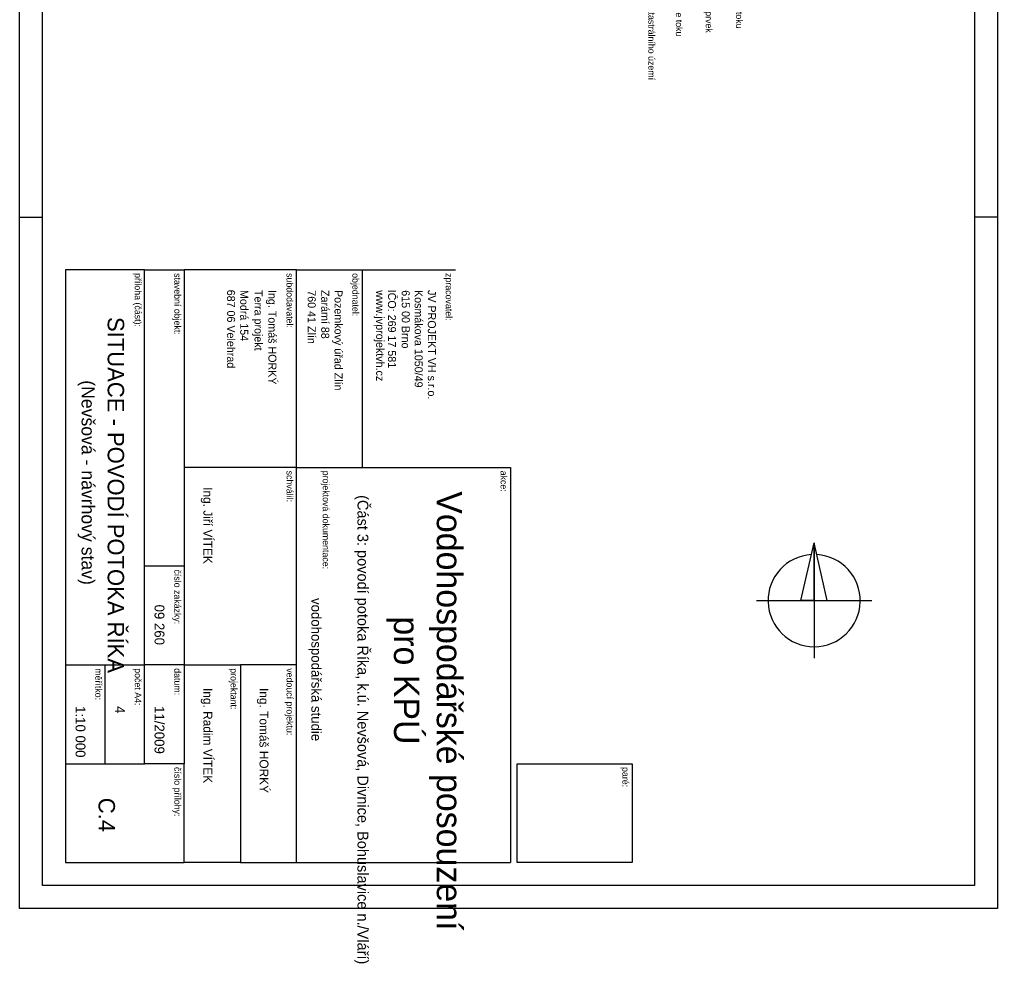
# Model space of a CAD drawing. Extents: x -510989 to -501240, y -1184665 to -1176089.
# Drawn here: x -510989 to -508019, y -1184665 to -1181798 of the extents above; entities that cross this region are included whole.
import ezdxf

# ---------------------------------------------------------------- set-up
doc = ezdxf.new("R2010")
doc.units = 0
for name, color, linetype in [('Implicitní', 7, 'Continuous'), ('legenda', 7, 'Continuous'), ('rozpiska', 7, 'Continuous')]:
    doc.layers.add(name, color=color, linetype=linetype)

# ---------------------------------------------------------------- blocks, each defined once
blk = doc.blocks.new('rozpiska-cary')
at = {"layer": 'Implicitní'}
for p, q in [((-0.03, -0.035), (-0.03, 0)), ((-0.03, 0), (0, 0)), ((0, 0), (0, -0.035)), ((0, -0.035), (-0.03, -0.035)), ((-0.12, -0.102), (-0.12, -0.037)), ((-0.12, -0.037), (0, -0.037)), ((0, -0.102), (0, -0.037)), ((-0.18, -0.082), (-0.18, -0.05365)), ((-0.18, -0.102), (-0.18, -0.082)), ((-0.18, -0.082), (-0.12, -0.082)), ((-0.12, -0.102), (-0.18, -0.102)), ((-0.18, -0.102), (-0.18, -0.1361)), ((-0.06, -0.102), (-0.12, -0.102)), ((-0.12, -0.102), (-0.12, -0.1361)), ((0, -0.102), (-0.06, -0.102)), ((-0.06, -0.102), (-0.06, -0.119)), ((0, -0.119), (0, -0.102)), ((-0.06, -0.13609), (-0.06, -0.119)), ((-0.06, -0.119), (0, -0.119)), ((0, -0.119), (0, -0.1361)), ((-0.18, -0.14809), (-0.18, -0.13609)), ((-0.18, -0.13609), (-0.09, -0.13609)), ((-0.09, -0.13609), (-0.09, -0.14809)), ((-0.09, -0.13609), (-0.06, -0.13609)), ((-0.06, -0.13609), (-0.06, -0.14809)), ((-0.06, -0.13609), (-0.03, -0.13609)), ((0, -0.13609), (-0.03, -0.13609)), ((-0.03, -0.13609), (-0.03, -0.14809)), ((0, -0.17209), (0, -0.13609)), ((-0.06, -0.14809), (-0.18, -0.14809)), ((-0.18, -0.14809), (-0.18, -0.17209)), ((-0.06, -0.17209), (-0.06, -0.14809)), ((-0.03, -0.14809), (-0.06, -0.14809)), ((-0.03, -0.16009), (-0.03, -0.14809)), ((-0.03, -0.16009), (-0.06, -0.16009)), ((-0.03, -0.17209), (-0.03, -0.16009)), ((-0.18, -0.17209), (-0.06, -0.17209)), ((-0.06, -0.17209), (-0.03, -0.17209)), ((-0.03, -0.17209), (0, -0.17209))]:
    blk.add_line(p, q, dxfattribs=at)

msp = doc.modelspace()

# ---------------------------------------------------------------- linework, layer by layer
at = {"layer": 'rozpiska'}
for p, q in [((-510989.09, -1182398), (-510919.09, -1182398)), ((-508019.09, -1182398), (-508089.09, -1182398)), ((-508615.85, -1183562.57), (-508575.85, -1183387.57)), ((-508575.85, -1183562.57), (-508575.85, -1183387.57)), ((-508535.85, -1183562.57), (-508575.85, -1183387.57)), ((-508750.85, -1183562.57), (-508400.85, -1183562.57)), ((-508575.85, -1183562.57), (-508615.85, -1183562.57)), ((-508575.85, -1183562.57), (-508575.85, -1183737.57)), ((-508575.85, -1183562.57), (-508535.85, -1183562.57))]:
    msp.add_line(p, q, dxfattribs=at)
for points in [[(-508019.09, -1176098), (-508019.09, -1184498), (-510989.09, -1184498), (-510989.09, -1176098)], [(-508089.09, -1176168), (-508089.09, -1184428), (-510919.09, -1184428), (-510919.09, -1176168)], [(-508575.85, -1183562.57), (-508535.85, -1183562.57), (-508575.85, -1183387.57)]]:
    msp.add_lwpolyline(points, close=True, dxfattribs=at)
msp.add_lwpolyline([(-508575.85, -1183562.57), (-508535.85, -1183562.57), (-508575.85, -1183387.57)], dxfattribs=at)
msp.add_arc((-508575.85, -1183562.57), 140, 93.29755, 86.70245, dxfattribs=at)

# ---------------------------------------------------------------- block references
at = {"layer": 'rozpiska', "xscale": 10000, "yscale": 10000, "rotation": -90.00000000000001}
msp.add_blockref('rozpiska-cary', (-509128.22, -1184358), dxfattribs=at)

# ---------------------------------------------------------------- texts
at = {"layer": 'legenda'}
for s, p in [('Hranice katastrálního území', (-509079.29, -1181648.76)), ('Revitalizace toku', (-508995.74, -1181646.93)), ('Interakční prvek', (-508904.97, -1181647.71)), ('Trasování toku', (-508813.03, -1181648.38))]:
    msp.add_text(s, height=20, rotation=270, dxfattribs=at).set_placement(p)
at = {"layer": 'rozpiska'}
for s, height, p in [('příloha (část):', 20, (-510639.09, -1182568)), ('stavební objekt:', 20, (-510519.09, -1182568)), ('subdodavatel:', 20, (-510178.22, -1182568)), ('objednatel:', 20, (-509978.22, -1182568)), ('zpracovatel:', 20, (-509694.76, -1182568)), ('687 06 Velehrad', 24.3, (-510358.84, -1182618.37)), ('Modrá 154', 24.3, (-510318.91, -1182619.22)), ('Terra projekt', 24.3, (-510275.44, -1182619.22)), ('Ing. Tomáš HORKÝ', 24.3, (-510233.34, -1182619.22)), ('760 41 Zlín', 24.3, (-510113.84, -1182620.09)), ('Zarámí 88', 24.3, (-510072.88, -1182619.22)), ('Pozemkový úřad Zlín', 24.3, (-510032.52, -1182619.22)), ('www.jvprojektvh.cz', 24.3, (-509906.04, -1182620.12)), ('IČO: 269 17 581', 24.3, (-509870.11, -1182618.28)), ('615 00 Brno', 24.3, (-509828.3, -1182619.94)), ('Kosmákova 1050/49', 24.3, (-509789.04, -1182619.22)), ('JV PROJEKT VH s.r.o.', 24.3, (-509749.06, -1182619.22)), ('SITUACE - POVODÍ POTOKA ŘÍKA', 50, (-510721.53, -1182701.26)), ('(Nevšová - návrhový stav)', 40, (-510800.68, -1182893.51)), ('schválil:', 20, (-510178.22, -1183168)), ('projektová dokumentace:', 20, (-510068.22, -1183168)), ('akce:', 20, (-509528.22, -1183168)), ('Ing. Jiří VÍTEK', 27, (-510430.65, -1183218)), ('(Část 3: povodí potoka Říka, k.ú. Nevšová, Divnice, Bohuslavice n./Vláří)', 33, (-509962.72, -1183242.23)), ('Vodohospodářské posouzení', 77, (-509721.84, -1183230.44)), ('číslo zakázky:', 20, (-510519.09, -1183468)), ('vodohospodářská studie', 30, (-510102.75, -1183554.71)), ('09 260', 30, (-510579.09, -1183574.75)), ('pro KPÚ', 77, (-509851.88, -1183610.39)), ('měřítko:', 20, (-510759.09, -1183768)), ('počet A4:', 20, (-510639.09, -1183768)), ('datum:', 20, (-510519.09, -1183768)), ('projektant:', 20, (-510348.22, -1183768)), ('vedoucí projektu:', 20, (-510178.22, -1183768)), ('Ing. Radim VÍTEK', 27, (-510430.65, -1183828)), ('Ing. Tomáš HORKÝ', 27, (-510260.22, -1183828)), ('1:10 000', 30, (-510818.97, -1183882.97)), ('4', 30, (-510699.09, -1183882.97)), ('11/2009', 30, (-510579.09, -1183882.97)), ('číslo přílohy:', 20, (-510519.09, -1184068)), ('paré:', 20, (-509158.22, -1184068)), ('C.4', 50, (-510749.31, -1184161.4))]:
    msp.add_text(s, height=height, rotation=270, dxfattribs=at).set_placement(p)

doc.saveas('drawing.dxf')
